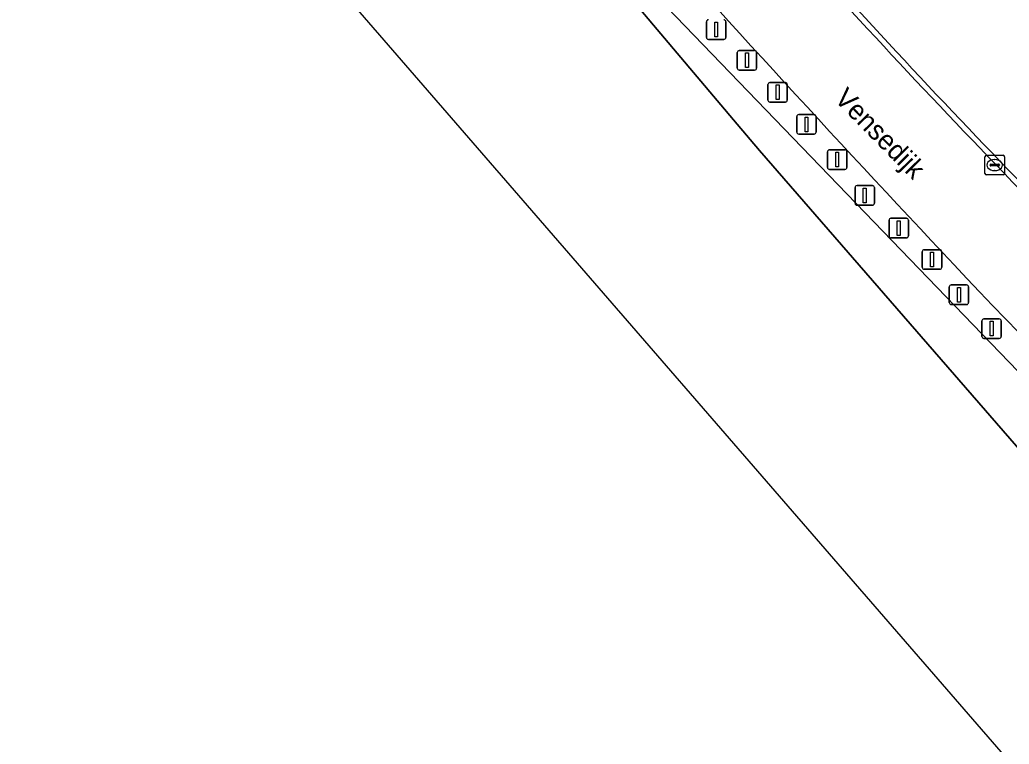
# Model space of a CAD drawing. Extents: x 156061 to 157804, y 383437 to 385640.
# Drawn here: x 156061.2 to 156111.7, y 385298.1 to 385335.2 of the extents above; entities that cross this region are included whole.
import ezdxf

# ---------------------------------------------------------------- set-up
doc = ezdxf.new("R2010")
doc.units = 0
for name, color, linetype in [('IMGEO_Afsluitpaal', 7, 'Continuous'), ('IMGEO_Berm_groen', 7, 'Continuous'), ('IMGEO_Groenvoorziening', 7, 'Continuous'), ('IMGEO_Kolk', 7, 'Continuous'), ('IMGEO_Openbare_ruimte_label', 7, 'Continuous'), ('IMGEO_Rijbaan_lokaal_gesloten', 7, 'Continuous'), ('IMGEO_Rijbaan_lokaal_open', 7, 'Continuous'), ('IMGEO_Waterloop', 7, 'Continuous')]:
    doc.layers.add(name, color=color, linetype=linetype)

msp = doc.modelspace()

# ---------------------------------------------------------------- linework, layer by layer
at = {"layer": 'IMGEO_Afsluitpaal'}
for p, q in [((156096.266, 385334.257), (156096.266, 385335.057)), ((156096.266, 385335.057), (156096.266, 385334.257)), ((156097.256, 385335.057), (156097.256, 385334.257)), ((156097.256, 385334.257), (156097.256, 385335.057)), ((156097.156, 385334.157), (156096.366, 385334.157)), ((156096.366, 385334.157), (156097.156, 385334.157)), ((156097.838, 385332.685), (156097.838, 385333.485)), ((156097.838, 385333.485), (156097.838, 385332.685)), ((156097.938, 385333.585), (156098.728, 385333.585)), ((156098.728, 385333.585), (156097.938, 385333.585)), ((156098.828, 385333.485), (156098.828, 385332.685)), ((156098.828, 385332.685), (156098.828, 385333.485)), ((156098.728, 385332.585), (156097.938, 385332.585)), ((156097.938, 385332.585), (156098.728, 385332.585)), ((156099.41, 385331.048), (156099.41, 385331.848)), ((156099.41, 385331.848), (156099.41, 385331.048)), ((156099.51, 385331.948), (156100.3, 385331.948)), ((156100.3, 385331.948), (156099.51, 385331.948)), ((156100.4, 385331.848), (156100.4, 385331.048)), ((156100.4, 385331.048), (156100.4, 385331.848)), ((156100.3, 385330.948), (156099.51, 385330.948)), ((156099.51, 385330.948), (156100.3, 385330.948)), ((156100.884, 385329.41), (156100.884, 385330.21)), ((156100.884, 385330.21), (156100.884, 385329.41)), ((156100.984, 385330.31), (156101.774, 385330.31)), ((156101.774, 385330.31), (156100.984, 385330.31)), ((156101.874, 385330.21), (156101.874, 385329.41)), ((156101.874, 385329.41), (156101.874, 385330.21)), ((156101.774, 385329.31), (156100.984, 385329.31)), ((156100.984, 385329.31), (156101.774, 385329.31)), ((156102.455, 385327.609), (156102.455, 385328.409)), ((156102.455, 385328.409), (156102.455, 385327.609)), ((156102.555, 385328.509), (156103.345, 385328.509)), ((156103.345, 385328.509), (156102.555, 385328.509)), ((156103.445, 385328.409), (156103.445, 385327.609)), ((156103.445, 385327.609), (156103.445, 385328.409)), ((156103.345, 385327.509), (156102.555, 385327.509)), ((156102.555, 385327.509), (156103.345, 385327.509)), ((156103.963, 385326.676), (156104.753, 385326.676)), ((156104.753, 385326.676), (156103.963, 385326.676)), ((156103.863, 385325.776), (156103.863, 385326.576)), ((156103.863, 385326.576), (156103.863, 385325.776)), ((156104.853, 385326.576), (156104.853, 385325.776)), ((156104.853, 385325.776), (156104.853, 385326.576)), ((156104.753, 385325.676), (156103.963, 385325.676)), ((156103.963, 385325.676), (156104.753, 385325.676)), ((156105.599, 385324.106), (156105.599, 385324.906)), ((156105.599, 385324.906), (156105.599, 385324.106)), ((156105.699, 385325.006), (156106.489, 385325.006)), ((156106.489, 385325.006), (156105.699, 385325.006)), ((156106.589, 385324.906), (156106.589, 385324.106)), ((156106.589, 385324.106), (156106.589, 385324.906)), ((156106.489, 385324.006), (156105.699, 385324.006)), ((156105.699, 385324.006), (156106.489, 385324.006)), ((156107.302, 385322.501), (156107.302, 385323.301)), ((156107.302, 385323.301), (156107.302, 385322.501)), ((156107.402, 385323.401), (156108.192, 385323.401)), ((156108.192, 385323.401), (156107.402, 385323.401)), ((156108.292, 385323.301), (156108.292, 385322.501)), ((156108.292, 385322.501), (156108.292, 385323.301)), ((156108.192, 385322.401), (156107.402, 385322.401)), ((156107.402, 385322.401), (156108.192, 385322.401)), ((156108.777, 385321.6), (156109.567, 385321.6)), ((156109.567, 385321.6), (156108.777, 385321.6)), ((156108.677, 385320.7), (156108.677, 385321.5)), ((156108.677, 385321.5), (156108.677, 385320.7)), ((156109.667, 385321.5), (156109.667, 385320.7)), ((156109.667, 385320.7), (156109.667, 385321.5)), ((156109.567, 385320.6), (156108.777, 385320.6)), ((156108.777, 385320.6), (156109.567, 385320.6)), ((156110.347, 385318.965), (156110.347, 385319.765)), ((156110.347, 385319.765), (156110.347, 385318.965)), ((156110.447, 385319.865), (156111.237, 385319.865)), ((156111.237, 385319.865), (156110.447, 385319.865)), ((156111.337, 385319.765), (156111.337, 385318.965)), ((156111.337, 385318.965), (156111.337, 385319.765)), ((156111.237, 385318.865), (156110.447, 385318.865)), ((156110.447, 385318.865), (156111.237, 385318.865))]:
    msp.add_line(p, q, dxfattribs=at)
for points in [[(156096.686, 385335.032), (156096.836, 385335.032), (156096.836, 385334.282), (156096.686, 385334.282), (156096.686, 385335.032)], [(156098.258, 385333.46), (156098.408, 385333.46), (156098.408, 385332.71), (156098.258, 385332.71), (156098.258, 385333.46)], [(156099.83, 385331.823), (156099.98, 385331.823), (156099.98, 385331.073), (156099.83, 385331.073), (156099.83, 385331.823)], [(156101.304, 385330.185), (156101.454, 385330.185), (156101.454, 385329.435), (156101.304, 385329.435), (156101.304, 385330.185)], [(156102.875, 385328.384), (156103.025, 385328.384), (156103.025, 385327.634), (156102.875, 385327.634), (156102.875, 385328.384)], [(156104.283, 385326.551), (156104.433, 385326.551), (156104.433, 385325.801), (156104.283, 385325.801), (156104.283, 385326.551)], [(156106.019, 385324.881), (156106.169, 385324.881), (156106.169, 385324.131), (156106.019, 385324.131), (156106.019, 385324.881)], [(156107.722, 385323.276), (156107.872, 385323.276), (156107.872, 385322.526), (156107.722, 385322.526), (156107.722, 385323.276)], [(156109.097, 385321.475), (156109.247, 385321.475), (156109.247, 385320.725), (156109.097, 385320.725), (156109.097, 385321.475)], [(156110.767, 385319.74), (156110.917, 385319.74), (156110.917, 385318.99), (156110.767, 385318.99), (156110.767, 385319.74)]]:
    msp.add_lwpolyline(points, dxfattribs=at)
for centre, start, end in [((156096.366, 385335.057), 90, 180), ((156096.366, 385335.057), 90, 180), ((156097.156, 385335.057), 0, 90), ((156097.156, 385335.057), 360, 90), ((156096.366, 385334.257), 180, 270), ((156096.366, 385334.257), 180, 270), ((156097.156, 385334.257), 270, 0), ((156097.156, 385334.257), 270, 0), ((156097.938, 385333.485), 90, 180), ((156097.938, 385333.485), 90, 180), ((156098.728, 385333.485), 0, 90), ((156098.728, 385333.485), 360, 90), ((156097.938, 385332.685), 180, 270), ((156097.938, 385332.685), 180, 270), ((156098.728, 385332.685), 270, 0), ((156098.728, 385332.685), 270, 0), ((156099.51, 385331.848), 90, 180), ((156099.51, 385331.848), 90, 180), ((156100.3, 385331.848), 0, 90), ((156100.3, 385331.848), 360, 90), ((156099.51, 385331.048), 180, 270), ((156099.51, 385331.048), 180, 270), ((156100.3, 385331.048), 270, 0), ((156100.3, 385331.048), 270, 0), ((156100.984, 385330.21), 90, 180), ((156100.984, 385330.21), 90, 180), ((156101.774, 385330.21), 0, 90), ((156101.774, 385330.21), 360, 90), ((156100.984, 385329.41), 180, 270), ((156100.984, 385329.41), 180, 270), ((156101.774, 385329.41), 270, 0), ((156101.774, 385329.41), 270, 0), ((156102.555, 385328.409), 90, 180), ((156102.555, 385328.409), 90, 180), ((156103.345, 385328.409), 0, 90), ((156103.345, 385328.409), 360, 90), ((156102.555, 385327.609), 180, 270), ((156102.555, 385327.609), 180, 270), ((156103.345, 385327.609), 270, 0), ((156103.345, 385327.609), 270, 0), ((156103.963, 385326.576), 90, 180), ((156103.963, 385326.576), 90, 180), ((156104.753, 385326.576), 0, 90), ((156104.753, 385326.576), 360, 90), ((156103.963, 385325.776), 180, 270), ((156103.963, 385325.776), 180, 270), ((156104.753, 385325.776), 270, 0), ((156104.753, 385325.776), 270, 0), ((156105.699, 385324.906), 90, 180), ((156105.699, 385324.906), 90, 180), ((156106.489, 385324.906), 0, 90), ((156106.489, 385324.906), 360, 90), ((156105.699, 385324.106), 180, 270), ((156105.699, 385324.106), 180, 270), ((156106.489, 385324.106), 270, 0), ((156106.489, 385324.106), 270, 0), ((156107.402, 385323.301), 90, 180), ((156107.402, 385323.301), 90, 180), ((156108.192, 385323.301), 0, 90), ((156108.192, 385323.301), 360, 90), ((156107.402, 385322.501), 180, 270), ((156107.402, 385322.501), 180, 270), ((156108.192, 385322.501), 270, 0), ((156108.192, 385322.501), 270, 0), ((156108.777, 385321.5), 90, 180), ((156108.777, 385321.5), 90, 180), ((156109.567, 385321.5), 0, 90), ((156109.567, 385321.5), 360, 90), ((156108.777, 385320.7), 180, 270), ((156108.777, 385320.7), 180, 270), ((156109.567, 385320.7), 270, 0), ((156109.567, 385320.7), 270, 0), ((156110.447, 385319.765), 90, 180), ((156110.447, 385319.765), 90, 180), ((156111.237, 385319.765), 0, 90), ((156111.237, 385319.765), 360, 90), ((156110.447, 385318.965), 180, 270), ((156110.447, 385318.965), 180, 270), ((156111.237, 385318.965), 270, 0), ((156111.237, 385318.965), 270, 0)]:
    msp.add_arc(centre, 0.1, start, end, dxfattribs=at)
at = {"layer": 'IMGEO_Berm_groen'}
msp.add_lwpolyline([(156090.572, 385342.654), (156088.242, 385345.342), (156086.7, 385344.464), (156091.934, 385338.209), (156118.185, 385310.964), (156135.945, 385294.822), (156156.716, 385276.694), (156178.807, 385257.413), (156194.589, 385243.638), (156195.449, 385241.419), (156196.62, 385234.817), (156197.006, 385232.642), (156197.517, 385230.649), (156199.397, 385226.773), (156203.958, 385221.849), (156215.178, 385210.126), (156226.868, 385197.417), (156233.383, 385189.899), (156240.967, 385180.78), (156244.391, 385176.164), (156248.071, 385171.713)], dxfattribs=at)
for centre, radius, start, end in [((156881.513, 386049.075), 1060.48, 221.76934, 223.237566), ((156311.141, 385512.453), 277.354, 223.19188, 229.47603)]:
    msp.add_arc(centre, radius, start, end, dxfattribs=at)
at = {"layer": 'IMGEO_Groenvoorziening'}
msp.add_lwpolyline([(156199.397, 385226.773), (156176.925, 385250), (156118.185, 385310.964), (156091.934, 385338.209), (156086.7, 385344.464), (156085.525, 385343.795), (156085.132, 385343.571), (156090.784, 385337.539), (156091.895, 385336.876), (156097.839, 385329.812), (156098.982, 385328.474), (156124.228, 385299.412), (156124.067, 385299.933), (156124.592, 385300.096), (156124.909, 385299.071), (156138.622, 385283.356), (156153.921, 385265.595), (156169.979, 385246.887), (156186.745, 385227.599), (156202.978, 385208.912)], dxfattribs=at)
for centre, radius, start, end in [((156445.013, 385650.323), 464.009, 220.62351, 222.91028), ((156444.762, 385648.913), 462.867, 222.80362, 227.53759)]:
    msp.add_arc(centre, radius, start, end, dxfattribs=at)
at = {"layer": 'IMGEO_Kolk'}
for p, q in [((156110.505, 385327.302), (156110.505, 385328.154)), ((156110.58, 385328.228), (156111.432, 385328.228)), ((156111.506, 385328.154), (156111.506, 385327.302)), ((156110.764, 385327.722), (156110.764, 385327.734)), ((156111.202, 385327.685), (156110.804, 385327.685)), ((156110.807, 385327.771), (156111.205, 385327.771)), ((156110.993, 385328.008), (156111.018, 385328.008)), ((156111.248, 385327.734), (156111.248, 385327.722)), ((156111.432, 385327.228), (156110.58, 385327.228)), ((156111.016, 385327.448), (156110.991, 385327.448))]:
    msp.add_line(p, q, dxfattribs=at)
for points in [[(156110.505, 385327.302), (156110.505, 385328.154)], [(156110.58, 385328.228), (156111.432, 385328.228)], [(156111.506, 385328.154), (156111.506, 385327.302)], [(156111.432, 385327.228), (156110.58, 385327.228)]]:
    msp.add_lwpolyline(points, dxfattribs=at)
for centre, radius, start, end in [((156110.582, 385328.152), 0.0765, 91.552, 178.448), ((156110.582, 385328.152), 0.0765, 91.552, 178.448), ((156111.43, 385328.152), 0.0765, 1.552, 88.448), ((156111.43, 385328.152), 0.0765, 1.552, 88.448), ((156110.804, 385327.731), 0.0403, 85.8775, 175.7526), ((156110.801, 385327.721), 0.0366, 178.938, 274.7102), ((156111.205, 385327.728), 0.043, 264.8664, 352.4533), ((156111.209, 385327.733), 0.0386, 1.7309, 96.639), ((156110.582, 385327.304), 0.0765, 181.552, 268.448), ((156110.582, 385327.304), 0.0765, 181.552, 268.448), ((156111.43, 385327.304), 0.0765, 271.552, 358.448), ((156111.43, 385327.304), 0.0765, 271.552, 358.448)]:
    msp.add_arc(centre, radius, start, end, dxfattribs=at)
for centre, major_axis, ratio, start_param, end_param in [((156110.992, 385327.728), (-0.387, 0.002), 0.722429, 4.712389, 7.853982), ((156111.017, 385327.728), (-0.39, 0.002), 0.717154, 1.570796, 4.712389)]:
    msp.add_ellipse(centre, major_axis=major_axis, ratio=ratio, start_param=start_param, end_param=end_param, dxfattribs=at)
at = {"layer": 'IMGEO_Rijbaan_lokaal_gesloten'}
for centre, radius, start, end in [((156440.532, 385646.589), 458.47, 220.51362, 222.94338), ((156881.513, 386049.075), 1060.48, 221.76934, 223.237566), ((156441.097, 385645.969), 458.462, 222.83854, 227.62493), ((156311.141, 385512.453), 277.354, 223.19188, 229.47603)]:
    msp.add_arc(centre, radius, start, end, dxfattribs=at)
at = {"layer": 'IMGEO_Rijbaan_lokaal_open'}
for centre, radius, start, end in [((156440.532, 385646.589), 458.47, 220.51362, 222.94338), ((156445.013, 385650.323), 464.009, 220.62351, 222.91028), ((156441.097, 385645.969), 458.462, 222.83854, 227.62493), ((156444.762, 385648.913), 462.867, 222.80362, 227.53759)]:
    msp.add_arc(centre, radius, start, end, dxfattribs=at)
at = {"layer": 'IMGEO_Waterloop'}
for points in [[(156069.338, 385360.86), (156061.156, 385355.592), (156648.236, 384678.397), (156868.628, 384425.309)], [(156124.228, 385299.412), (156098.982, 385328.474), (156097.839, 385329.812), (156091.895, 385336.876)]]:
    msp.add_lwpolyline(points, dxfattribs=at)

# ---------------------------------------------------------------- texts
at = {"layer": 'IMGEO_Openbare_ruimte_label'}
msp.add_text('Vensedijk', height=1, rotation=314.5948, dxfattribs=at).set_placement((156102.757, 385331.069))

doc.saveas('drawing.dxf')
